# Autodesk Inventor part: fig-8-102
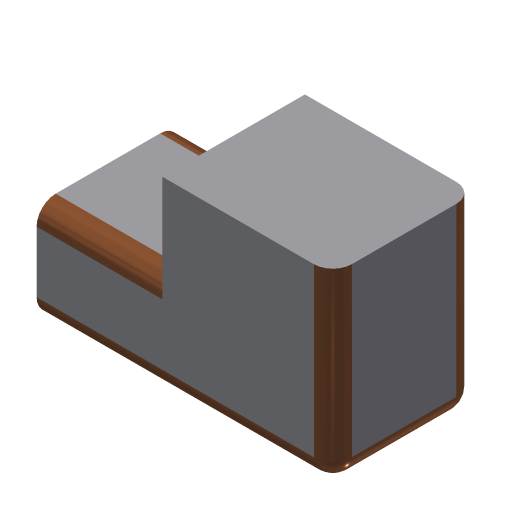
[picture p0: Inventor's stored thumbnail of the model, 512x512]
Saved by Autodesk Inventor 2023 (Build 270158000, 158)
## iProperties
Part Number: fig-8-102
Document SubType Name: Modeling
Created: 2002-12
Designer: deepak
Density: 1 g/cm^3
Material: Generic
Appearance: Default
Control State: 0
Master: False
Checked Out: False
Shininess: 64.0
Length Units: 11269
Angle Units: 11279
Time Units: 11290
Mass Units: 11283
Length Display Precision: 3
Angle Display Precision: 2
Compacted: True
Density: 0.0
Volumn: 0.0
Area: 0.0
PropertySet Name: Model Information
Author: deepak
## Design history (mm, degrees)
sketch "Sketch1"
  geometry: L1 (-26.972, 23.346)-(8.906, 23.346); L2 (8.906, 23.346)-(8.906, 5.025); L3 (8.906, -15.84)-(-26.972, -15.84); L4 (-26.972, -15.84)-(-26.972, 23.346); L5 (8.906, -15.84)-(35.369, -15.84); L6 (35.369, -15.84)-(35.369, 5.025); L7 (35.369, 5.025)-(8.906, 5.025)
  constraints: 14 end point, 3 parallel, 2 horizontal, 2 perpendicular
extrude "Extrusion1" new body sketch "Sketch1" stored distance "d0" = 30; taper "d1" = 0 deg
fillet "Fillet1" dims "d2" = 4, "d3" = 4
delete_face "Delete Face1"
delete_face "Delete Face2"
delete_face "Delete Face3"
body "Solid1"
